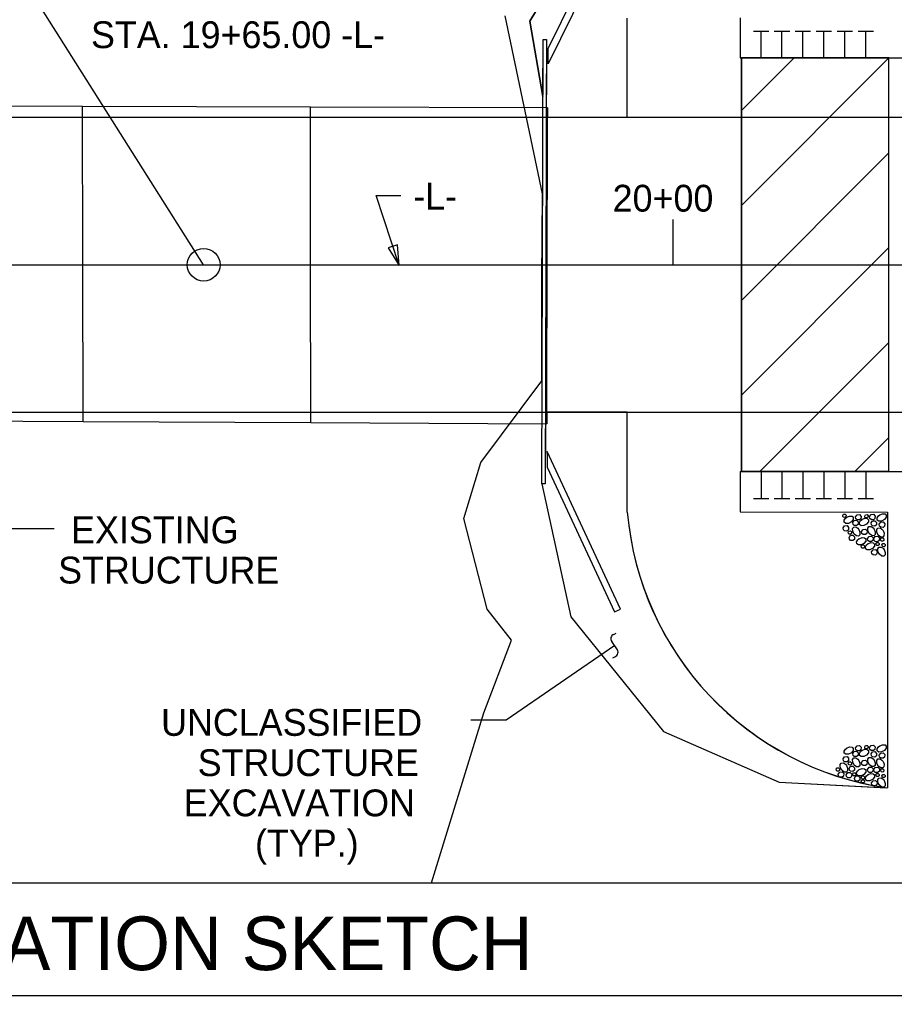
# Model space of a CAD drawing. Extents: x 985 to 1514, y -701 to -21.
# Drawn here: x 1103 to 1168.3, y -465.7 to -392.9 of the extents above; entities that cross this region are included whole.
import ezdxf

# ---------------------------------------------------------------- set-up
doc = ezdxf.new("R2010")
doc.units = 0
for name, color, linetype in [('Arrowhead Terminators CELL', 7, 'Continuous'), ('Default', 7, 'Continuous'), ('Dimension Lines', 7, 'Continuous'), ('Exist Hydro Stream or Body of Water', 7, 'Continuous'), ('Exist Structure Major Bridge WW', 7, 'Continuous'), ('Exist Structure Major Deck Tunnel Box Culvert', 7, 'Continuous'), ('Mis Object Lines', 7, 'Continuous'), ('Miscellaneous Lines CELL', 7, 'Continuous'), ('Plan Sheet CELL', 7, 'Continuous'), ('Prop EOT', 7, 'Continuous'), ('Prop Horizontal Alignment', 7, 'Continuous'), ('Prop Horizontal Alignment Tick Large', 7, 'Continuous'), ('Sup Concrete Girder Lines', 7, 'Continuous'), ('Text', 7, 'Continuous'), ('Title Text', 7, 'Continuous')]:
    doc.layers.add(name, color=color, linetype=linetype)

msp = doc.modelspace()

# ---------------------------------------------------------------- linework, layer by layer
at = {"layer": 'Arrowhead Terminators CELL'}
for p, q in [((1147.348, -438.738), (1147.544, -438.638)), ((1147.585, -439.805), (1147.209, -439.259)), ((1147.291, -440.47), (1147.441, -440.401))]:
    msp.add_line(p, q, dxfattribs=at)
msp.add_lwpolyline([(1131.348, -411.222), (1131.235, -409.68), (1130.522, -409.915)], close=True, dxfattribs=at)
for centre, radius, start, end in [((1147.464, -439.051), 0.331, 110.38616, 218.67174), ((1147.304, -440.05), 0.373, 291.31771, 41.11659)]:
    msp.add_arc(centre, radius, start, end, dxfattribs=at)
at = {"layer": 'Default'}
for p, q in [((1141.093, -393.022), (1146.61, -383.851)), ((1142.074, -398.634), (1141.093, -393.022)), ((1157.763, -393.758), (1158.908, -393.758)), ((1158.336, -395.758), (1158.336, -393.758)), ((1159.325, -393.758), (1160.471, -393.758)), ((1159.898, -395.758), (1159.898, -393.758)), ((1160.888, -393.758), (1162.033, -393.758)), ((1161.461, -395.758), (1161.461, -393.758)), ((1162.45, -393.758), (1163.596, -393.758)), ((1163.023, -395.758), (1163.023, -393.758)), ((1164.013, -393.758), (1165.158, -393.758)), ((1164.586, -395.758), (1164.586, -393.758)), ((1165.575, -393.758), (1166.721, -393.758)), ((1166.148, -395.758), (1166.148, -393.758)), ((1156.773, -395.758), (1175.523, -395.758)), ((1156.873, -395.758), (1156.873, -426.592)), ((1156.873, -426.592), (1156.873, -395.758)), ((1156.873, -395.758), (1167.873, -395.758)), ((1156.773, -426.592), (1175.523, -426.592)), ((1156.873, -426.592), (1167.873, -426.592)), ((1158.336, -426.592), (1158.336, -428.592)), ((1159.898, -426.592), (1159.898, -428.592)), ((1161.461, -426.592), (1161.461, -428.592)), ((1163.023, -426.592), (1163.023, -428.592)), ((1164.586, -426.592), (1164.586, -428.592)), ((1166.148, -426.592), (1166.148, -428.592)), ((1141.991, -427.502), (1144.162, -437.414)), ((1157.763, -428.592), (1158.908, -428.592)), ((1159.325, -428.592), (1160.471, -428.592)), ((1160.888, -428.592), (1162.033, -428.592)), ((1162.45, -428.592), (1163.596, -428.592)), ((1164.013, -428.592), (1165.158, -428.592)), ((1165.575, -428.592), (1166.721, -428.592)), ((1144.162, -437.414), (1151.051, -445.982))]:
    msp.add_line(p, q, dxfattribs=at)
msp.add_lwpolyline([(1151.051, -445.982), (1159.699, -449.748), (1167.773, -450.175)], dxfattribs=at)
at = {"layer": 'Dimension Lines'}
for p, q in [((1146.61, -383.851), (1141.093, -393.022)), ((1116.773, -411.175), (1104.687, -392.069)), ((1141.093, -393.022), (1142.074, -398.634)), ((1142.419, -400.175), (1148.364, -400.175)), ((1131.348, -411.222), (1129.629, -406.004)), ((1129.629, -406.004), (1131.466, -406.004)), ((1148.364, -422.175), (1142.356, -422.175)), ((1148.364, -429.616), (1148.364, -422.175)), ((1141.991, -427.502), (1144.162, -437.414)), ((1148.364, -429.623), (1148.364, -429.616)), ((1099.867, -430.828), (1105.638, -430.828)), ((1144.162, -437.414), (1151.051, -445.982)), ((1147.429, -439.565), (1139.338, -445.137)), ((1139.338, -445.137), (1136.685, -445.137))]:
    msp.add_line(p, q, dxfattribs=at)
for points in [[(1148.364, -400.175), (1148.364, -392.79), (1148.364, -392.783)], [(1142.074, -398.634), (1142.086, -394.381), (1142.336, -394.382), (1142.321, -399.479)], [(1142.321, -399.479), (1142.421, -399.479), (1142.419, -400.175)], [(1142.356, -422.175), (1142.354, -423.031), (1142.254, -423.031)], [(1142.254, -423.031), (1142.241, -427.503), (1141.991, -427.502)], [(1151.051, -445.982), (1159.699, -449.748), (1167.695, -450.171)]]:
    msp.add_lwpolyline(points, dxfattribs=at)
msp.add_circle((1116.773, -411.175), 1.22, dxfattribs=at)
msp.add_arc((1171.027, -427.669), 22.747, 184.92778, 261.57569, dxfattribs=at)
at = {"layer": 'Exist Hydro Stream or Body of Water'}
for points in [[(1137.431, -425.921), (1141.989, -419.828), (1141.981, -412.265), (1142.035, -405.886), (1139.255, -392.628)], [(1133.751, -457.245), (1137.656, -444.578), (1139.721, -439.174), (1137.917, -436.842), (1136.178, -430.103), (1137.431, -425.921)]]:
    msp.add_lwpolyline(points, dxfattribs=at)
at = {"layer": 'Exist Structure Major Bridge WW'}
for points in [[(1142.466, -396.199), (1142.47, -395.06), (1147.485, -384.876), (1147.933, -385.097), (1142.466, -396.199)], [(1142.086, -394.381), (1142.336, -394.382), (1142.241, -427.503), (1141.991, -427.502), (1142.086, -394.381)], [(1142.383, -425.089), (1142.38, -426.263), (1147.415, -437.051), (1147.868, -436.84), (1142.383, -425.089)]]:
    msp.add_lwpolyline(points, dxfattribs=at)
at = {"layer": 'Exist Structure Major Deck Tunnel Box Culvert'}
for points in [[(1089.779, -417.969), (1089.79, -421.084), (1089.795, -422.771), (1107.784, -422.86), (1124.759, -422.944), (1142.354, -423.031), (1142.36, -420.765), (1142.388, -411.087), (1142.415, -401.584), (1142.421, -399.479), (1124.744, -399.43), (1107.731, -399.382), (1089.718, -399.332)], [(1107.784, -422.86), (1107.757, -411.014), (1107.731, -399.382)], [(1124.759, -422.944), (1124.752, -410.979), (1124.744, -399.43)]]:
    msp.add_lwpolyline(points, dxfattribs=at)
at = {"layer": 'Mis Object Lines'}
for p, q in [((1156.873, -395.758), (1156.873, -426.592)), ((1167.873, -395.758), (1156.873, -395.758)), ((1156.873, -406.758), (1167.873, -395.758)), ((1156.873, -399.687), (1160.802, -395.758)), ((1167.873, -426.592), (1167.873, -395.758)), ((1156.873, -413.829), (1167.873, -402.829)), ((1156.873, -420.9), (1167.873, -409.9)), ((1158.253, -426.592), (1167.873, -416.972)), ((1165.324, -426.592), (1167.873, -424.043)), ((1167.873, -426.592), (1156.873, -426.592))]:
    msp.add_line(p, q, dxfattribs=at)
at = {"layer": 'Miscellaneous Lines CELL'}
for points in [[(1164.43, -429.87), (1164.497, -429.774), (1164.605, -429.768), (1164.679, -429.846), (1164.668, -429.954), (1164.602, -430.009), (1164.496, -430.002), (1164.446, -429.953), (1164.43, -429.87)], [(1164.72, -429.993), (1164.93, -429.91), (1165.122, -429.926), (1165.214, -430.013), (1165.211, -430.17), (1165.072, -430.347), (1164.858, -430.455), (1164.655, -430.458), (1164.541, -430.377), (1164.531, -430.216), (1164.623, -430.072), (1164.729, -429.987)], [(1165.384, -429.972), (1165.496, -429.813), (1165.675, -429.803), (1165.799, -429.932), (1165.781, -430.112), (1165.671, -430.204), (1165.494, -430.192), (1165.411, -430.111), (1165.384, -429.972)], [(1166.064, -429.907), (1166.131, -429.811), (1166.239, -429.805), (1166.313, -429.882), (1166.302, -429.991), (1166.236, -430.046), (1166.13, -430.038), (1166.08, -429.99), (1166.064, -429.907)], [(1166.431, -429.948), (1166.543, -429.789), (1166.722, -429.779), (1166.847, -429.908), (1166.829, -430.088), (1166.718, -430.18), (1166.541, -430.167), (1166.458, -430.087), (1166.431, -429.948)], [(1167.183, -429.821), (1167.393, -429.738), (1167.585, -429.754), (1167.677, -429.841), (1167.674, -429.998), (1167.535, -430.175), (1167.32, -430.282), (1167.118, -430.286), (1167.004, -430.205), (1166.993, -430.044), (1167.086, -429.9), (1167.192, -429.815)], [(1164.455, -430.794), (1164.567, -430.635), (1164.746, -430.624), (1164.87, -430.753), (1164.852, -430.934), (1164.742, -431.026), (1164.565, -431.013), (1164.482, -430.933), (1164.455, -430.794)], [(1165.631, -430.907), (1165.714, -431.116), (1165.698, -431.309), (1165.611, -431.4), (1165.454, -431.397), (1165.277, -431.258), (1165.169, -431.044), (1165.166, -430.841), (1165.247, -430.728), (1165.408, -430.717), (1165.552, -430.809), (1165.636, -430.915)], [(1165.173, -430.394), (1165.285, -430.235), (1165.464, -430.224), (1165.589, -430.353), (1165.571, -430.534), (1165.46, -430.626), (1165.283, -430.613), (1165.2, -430.533), (1165.173, -430.394)], [(1165.859, -430.162), (1166.069, -430.079), (1166.261, -430.096), (1166.353, -430.183), (1166.35, -430.339), (1166.211, -430.517), (1165.996, -430.624), (1165.794, -430.628), (1165.68, -430.547), (1165.669, -430.385), (1165.762, -430.241), (1165.868, -430.157)], [(1166.77, -430.879), (1166.853, -431.089), (1166.836, -431.282), (1166.749, -431.373), (1166.593, -431.37), (1166.415, -431.231), (1166.308, -431.017), (1166.305, -430.814), (1166.386, -430.7), (1166.547, -430.69), (1166.691, -430.782), (1166.775, -430.888)], [(1166.537, -430.425), (1166.649, -430.266), (1166.828, -430.256), (1166.952, -430.385), (1166.934, -430.565), (1166.823, -430.657), (1166.647, -430.645), (1166.564, -430.564), (1166.537, -430.425)], [(1167.149, -430.523), (1167.261, -430.364), (1167.44, -430.353), (1167.565, -430.482), (1167.547, -430.663), (1167.436, -430.755), (1167.259, -430.742), (1167.176, -430.662), (1167.149, -430.523)], [(1164.84, -431.121), (1164.907, -431.025), (1165.014, -431.019), (1165.089, -431.096), (1165.078, -431.205), (1165.012, -431.26), (1164.906, -431.252), (1164.856, -431.204), (1164.84, -431.121)], [(1164.897, -431.506), (1165.009, -431.346), (1165.188, -431.336), (1165.312, -431.465), (1165.294, -431.646), (1165.184, -431.738), (1165.007, -431.725), (1164.924, -431.644), (1164.897, -431.506)], [(1165.832, -431.065), (1165.944, -430.906), (1166.123, -430.896), (1166.248, -431.024), (1166.23, -431.205), (1166.119, -431.297), (1165.942, -431.284), (1165.859, -431.204), (1165.832, -431.065)], [(1166.281, -431.585), (1166.393, -431.425), (1166.572, -431.415), (1166.696, -431.544), (1166.678, -431.725), (1166.568, -431.817), (1166.391, -431.804), (1166.308, -431.723), (1166.281, -431.585)], [(1166.742, -431.591), (1166.854, -431.432), (1167.033, -431.422), (1167.157, -431.551), (1167.139, -431.732), (1167.028, -431.823), (1166.852, -431.811), (1166.769, -431.73), (1166.742, -431.592)], [(1167.434, -430.981), (1167.517, -431.191), (1167.501, -431.383), (1167.414, -431.475), (1167.257, -431.472), (1167.08, -431.333), (1166.972, -431.118), (1166.969, -430.916), (1167.05, -430.802), (1167.211, -430.791), (1167.355, -430.884), (1167.439, -430.99)], [(1165.656, -431.599), (1165.865, -431.516), (1166.058, -431.533), (1166.149, -431.62), (1166.147, -431.776), (1166.008, -431.954), (1165.793, -432.061), (1165.591, -432.065), (1165.477, -431.984), (1165.466, -431.822), (1165.558, -431.678), (1165.664, -431.594)], [(1165.807, -432.161), (1165.874, -432.065), (1165.981, -432.059), (1166.056, -432.136), (1166.045, -432.245), (1165.979, -432.3), (1165.873, -432.292), (1165.823, -432.244), (1165.807, -432.161)], [(1166.306, -431.974), (1166.516, -431.891), (1166.708, -431.907), (1166.8, -431.994), (1166.797, -432.151), (1166.658, -432.328), (1166.443, -432.435), (1166.241, -432.439), (1166.127, -432.358), (1166.116, -432.197), (1166.209, -432.053), (1166.315, -431.968)], [(1166.905, -431.977), (1166.972, -431.881), (1167.079, -431.875), (1167.154, -431.953), (1167.143, -432.061), (1167.077, -432.116), (1166.971, -432.108), (1166.921, -432.06), (1166.905, -431.977)], [(1167.251, -431.641), (1167.319, -431.545), (1167.426, -431.539), (1167.501, -431.616), (1167.49, -431.725), (1167.424, -431.78), (1167.318, -431.772), (1167.268, -431.724), (1167.252, -431.641)], [(1167.346, -432.056), (1167.413, -431.96), (1167.521, -431.954), (1167.595, -432.031), (1167.584, -432.14), (1167.518, -432.195), (1167.412, -432.187), (1167.362, -432.139), (1167.346, -432.056)], [(1166.581, -432.582), (1166.693, -432.423), (1166.872, -432.412), (1166.996, -432.541), (1166.978, -432.722), (1166.867, -432.814), (1166.691, -432.801), (1166.608, -432.721), (1166.581, -432.582)], [(1167.515, -432.411), (1167.598, -432.621), (1167.582, -432.813), (1167.495, -432.905), (1167.339, -432.902), (1167.161, -432.763), (1167.054, -432.549), (1167.05, -432.346), (1167.131, -432.232), (1167.292, -432.222), (1167.436, -432.314), (1167.521, -432.42)], [(1164.72, -447.209), (1164.93, -447.126), (1165.122, -447.143), (1165.214, -447.23), (1165.211, -447.386), (1165.072, -447.563), (1164.858, -447.671), (1164.655, -447.674), (1164.541, -447.593), (1164.531, -447.432), (1164.623, -447.288), (1164.729, -447.204)], [(1165.173, -447.61), (1165.285, -447.451), (1165.464, -447.441), (1165.589, -447.57), (1165.571, -447.75), (1165.46, -447.842), (1165.283, -447.829), (1165.2, -447.749), (1165.173, -447.61)], [(1165.384, -447.189), (1165.496, -447.029), (1165.675, -447.019), (1165.799, -447.148), (1165.781, -447.329), (1165.671, -447.421), (1165.494, -447.408), (1165.411, -447.327), (1165.384, -447.189)], [(1165.859, -447.378), (1166.069, -447.295), (1166.261, -447.312), (1166.353, -447.399), (1166.35, -447.555), (1166.211, -447.733), (1165.996, -447.84), (1165.794, -447.844), (1165.68, -447.763), (1165.669, -447.602), (1165.762, -447.458), (1165.868, -447.373)], [(1166.064, -447.123), (1166.131, -447.027), (1166.239, -447.021), (1166.313, -447.099), (1166.302, -447.207), (1166.236, -447.262), (1166.13, -447.255), (1166.08, -447.206), (1166.064, -447.123)], [(1166.431, -447.164), (1166.543, -447.005), (1166.722, -446.995), (1166.847, -447.124), (1166.829, -447.304), (1166.718, -447.396), (1166.541, -447.384), (1166.458, -447.303), (1166.431, -447.164)], [(1167.183, -447.037), (1167.393, -446.954), (1167.585, -446.97), (1167.677, -447.058), (1167.674, -447.214), (1167.535, -447.391), (1167.32, -447.499), (1167.118, -447.502), (1167.004, -447.421), (1166.993, -447.26), (1167.086, -447.116), (1167.192, -447.032)], [(1164.455, -448.01), (1164.567, -447.851), (1164.746, -447.841), (1164.87, -447.97), (1164.852, -448.15), (1164.742, -448.242), (1164.565, -448.229), (1164.482, -448.149), (1164.455, -448.01)], [(1165.631, -448.123), (1165.714, -448.332), (1165.698, -448.525), (1165.611, -448.616), (1165.454, -448.614), (1165.277, -448.475), (1165.169, -448.26), (1165.166, -448.058), (1165.247, -447.944), (1165.408, -447.933), (1165.552, -448.025), (1165.636, -448.131)], [(1165.832, -448.281), (1165.944, -448.122), (1166.123, -448.112), (1166.248, -448.241), (1166.23, -448.421), (1166.119, -448.513), (1165.942, -448.5), (1165.859, -448.42), (1165.832, -448.281)], [(1166.77, -448.096), (1166.853, -448.305), (1166.836, -448.498), (1166.749, -448.589), (1166.593, -448.586), (1166.415, -448.447), (1166.308, -448.233), (1166.305, -448.031), (1166.386, -447.917), (1166.547, -447.906), (1166.691, -447.998), (1166.775, -448.104)], [(1166.537, -447.642), (1166.649, -447.482), (1166.828, -447.472), (1166.952, -447.601), (1166.934, -447.782), (1166.823, -447.874), (1166.647, -447.861), (1166.564, -447.78), (1166.537, -447.642)], [(1167.434, -448.197), (1167.517, -448.407), (1167.501, -448.599), (1167.414, -448.691), (1167.257, -448.688), (1167.08, -448.549), (1166.972, -448.335), (1166.969, -448.132), (1167.05, -448.018), (1167.211, -448.008), (1167.355, -448.1), (1167.439, -448.206)], [(1167.149, -447.739), (1167.261, -447.58), (1167.44, -447.57), (1167.565, -447.699), (1167.547, -447.879), (1167.436, -447.971), (1167.259, -447.958), (1167.176, -447.878), (1167.149, -447.739)], [(1163.942, -448.786), (1164.009, -448.69), (1164.117, -448.684), (1164.191, -448.762), (1164.181, -448.87), (1164.114, -448.925), (1164.008, -448.918), (1163.958, -448.869), (1163.942, -448.786)], [(1164.706, -448.501), (1164.789, -448.711), (1164.772, -448.904), (1164.685, -448.995), (1164.529, -448.992), (1164.352, -448.853), (1164.244, -448.639), (1164.241, -448.436), (1164.322, -448.323), (1164.483, -448.312), (1164.627, -448.404), (1164.711, -448.51)], [(1164.84, -448.337), (1164.907, -448.241), (1165.014, -448.235), (1165.089, -448.312), (1165.078, -448.421), (1165.012, -448.476), (1164.906, -448.468), (1164.856, -448.42), (1164.84, -448.337)], [(1164.897, -448.722), (1165.009, -448.563), (1165.188, -448.552), (1165.312, -448.681), (1165.294, -448.862), (1165.184, -448.954), (1165.007, -448.941), (1164.924, -448.86), (1164.897, -448.722)], [(1165.656, -448.815), (1165.865, -448.732), (1166.058, -448.749), (1166.149, -448.836), (1166.147, -448.992), (1166.008, -449.17), (1165.793, -449.277), (1165.591, -449.281), (1165.477, -449.2), (1165.466, -449.039), (1165.558, -448.895), (1165.664, -448.81)], [(1166.281, -448.801), (1166.393, -448.642), (1166.572, -448.631), (1166.696, -448.76), (1166.678, -448.941), (1166.568, -449.033), (1166.391, -449.02), (1166.308, -448.939), (1166.281, -448.801)], [(1166.742, -448.808), (1166.854, -448.648), (1167.033, -448.638), (1167.157, -448.767), (1167.139, -448.948), (1167.028, -449.04), (1166.852, -449.027), (1166.769, -448.946), (1166.742, -448.808)], [(1167.251, -448.857), (1167.319, -448.761), (1167.426, -448.755), (1167.501, -448.833), (1167.49, -448.941), (1167.424, -448.996), (1167.318, -448.988), (1167.268, -448.94), (1167.252, -448.857)], [(1164.088, -449.151), (1164.2, -448.992), (1164.379, -448.981), (1164.503, -449.11), (1164.485, -449.291), (1164.375, -449.383), (1164.198, -449.37), (1164.115, -449.289), (1164.088, -449.151)], [(1164.692, -449.194), (1164.804, -449.035), (1164.983, -449.025), (1165.107, -449.154), (1165.089, -449.334), (1164.978, -449.426), (1164.802, -449.414), (1164.719, -449.333), (1164.692, -449.194)], [(1165.153, -449.149), (1165.22, -449.053), (1165.327, -449.047), (1165.402, -449.125), (1165.391, -449.233), (1165.325, -449.288), (1165.219, -449.28), (1165.169, -449.232), (1165.153, -449.149)], [(1165.294, -449.442), (1165.406, -449.282), (1165.585, -449.272), (1165.709, -449.401), (1165.691, -449.582), (1165.581, -449.674), (1165.404, -449.661), (1165.321, -449.58), (1165.294, -449.442)], [(1165.807, -449.377), (1165.874, -449.281), (1165.981, -449.275), (1166.056, -449.353), (1166.045, -449.461), (1165.979, -449.516), (1165.873, -449.509), (1165.823, -449.46), (1165.807, -449.377)], [(1165.807, -449.665), (1165.874, -449.57), (1165.981, -449.564), (1166.056, -449.641), (1166.045, -449.749), (1165.979, -449.805), (1165.873, -449.797), (1165.823, -449.749), (1165.807, -449.666)], [(1166.306, -449.19), (1166.516, -449.107), (1166.708, -449.123), (1166.8, -449.21), (1166.797, -449.367), (1166.658, -449.544), (1166.443, -449.652), (1166.241, -449.655), (1166.127, -449.574), (1166.116, -449.413), (1166.209, -449.269), (1166.315, -449.185)], [(1166.581, -449.798), (1166.693, -449.639), (1166.872, -449.629), (1166.996, -449.758), (1166.978, -449.938), (1166.867, -450.03), (1166.691, -450.017), (1166.608, -449.937), (1166.581, -449.798)], [(1166.905, -449.193), (1166.972, -449.098), (1167.079, -449.091), (1167.154, -449.169), (1167.143, -449.277), (1167.077, -449.332), (1166.971, -449.325), (1166.921, -449.276), (1166.905, -449.193)], [(1167.515, -449.628), (1167.598, -449.837), (1167.582, -450.03), (1167.495, -450.121), (1167.339, -450.118), (1167.161, -449.979), (1167.054, -449.765), (1167.05, -449.562), (1167.131, -449.449), (1167.292, -449.438), (1167.436, -449.53), (1167.521, -449.636)], [(1167.346, -449.272), (1167.413, -449.176), (1167.521, -449.17), (1167.595, -449.248), (1167.584, -449.356), (1167.518, -449.411), (1167.412, -449.403), (1167.362, -449.355), (1167.346, -449.272)]]:
    msp.add_lwpolyline(points, dxfattribs=at)
at = {"layer": 'Plan Sheet CELL'}
msp.add_line((1002.096, -457.245), (1243.069, -457.245), dxfattribs=at)
msp.add_lwpolyline([(1002.096, -465.652), (1243.069, -465.652), (1243.069, -355.46)], dxfattribs=at)
at = {"layer": 'Prop EOT'}
for p, q in [((1002.096, -400.175), (1243.069, -400.175)), ((1002.096, -422.175), (1243.069, -422.175))]:
    msp.add_line(p, q, dxfattribs=at)
at = {"layer": 'Prop Horizontal Alignment'}
msp.add_line((1002.096, -411.175), (1172.926, -411.175), dxfattribs=at)
at = {"layer": 'Prop Horizontal Alignment Tick Large'}
msp.add_line((1151.773, -411.175), (1151.773, -407.811), dxfattribs=at)
at = {"layer": 'Sup Concrete Girder Lines'}
for p, q in [((1156.773, -392.758), (1156.773, -395.758)), ((1156.773, -426.592), (1156.773, -429.592)), ((1156.773, -429.592), (1167.773, -429.623)), ((1167.773, -429.623), (1167.773, -450.175))]:
    msp.add_line(p, q, dxfattribs=at)
for centre in [(1171.027, -427.662), (1171.027, -427.669)]:
    msp.add_arc(centre, 22.747, 184.92778, 261.77484, dxfattribs=at)

# ---------------------------------------------------------------- texts
at = {"layer": 'Text'}
for s, p in [('STA. 19+65.00 -L-', (1108.372, -395.026)), ('-L-', (1132.402, -407.063)), ('20+00', (1147.27, -407.215)), ('EXISTING', (1106.89, -431.94)), ('STRUCTURE', (1105.922, -434.94)), ('UNCLASSIFIED', (1113.597, -446.295)), ('STRUCTURE', (1116.329, -449.295)), ('EXCAVATION', (1115.29, -452.295)), ('(TYP.)', (1120.605, -455.295))]:
    msp.add_text(s, height=2, dxfattribs=at).set_placement(p)
at = {"layer": 'Title Text'}
msp.add_text('LOCATION SKETCH', height=4, dxfattribs=at).set_placement((1090.783, -463.764))

doc.saveas('drawing.dxf')
